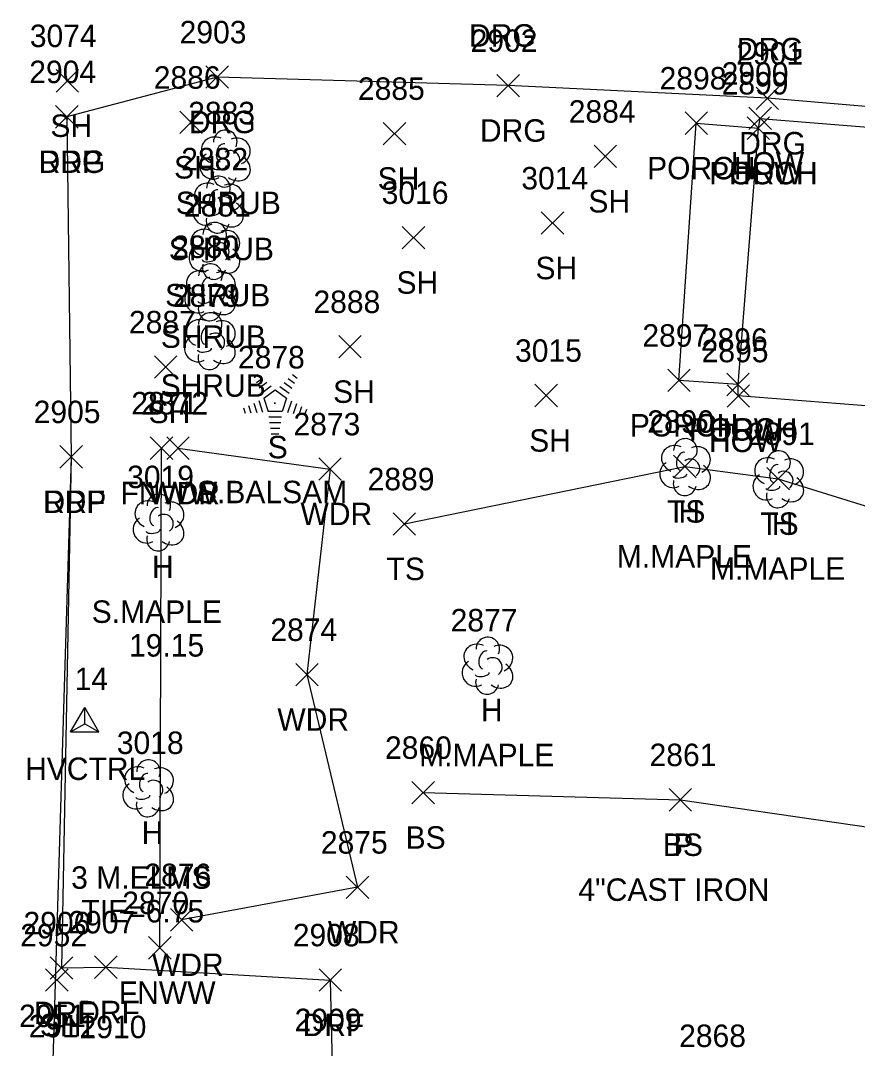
# Model space of a CAD drawing. Extents: x 1609623 to 1616187, y 756677 to 762826.
# Drawn here: x 1610617.9 to 1610692.4, y 762084.8 to 762176.3 of the extents above; entities that cross this region are included whole.
import ezdxf

# ---------------------------------------------------------------- set-up
doc = ezdxf.new("R2010")
doc.units = 0
for name, color, linetype in [('C_A', 7, 'Continuous'), ('C_I', 7, 'Continuous'), ('CPSM', 7, 'Continuous'), ('D_A', 7, 'Continuous'), ('D_C', 7, 'Continuous'), ('D_I', 7, 'Continuous'), ('D_TIC', 7, 'Continuous'), ('L_A', 7, 'Continuous'), ('L_C', 7, 'Continuous'), ('L_I', 7, 'Continuous'), ('L_TIC', 7, 'Continuous'), ('LAWA', 7, 'Continuous'), ('LBC', 7, 'Continuous'), ('LBF', 7, 'Continuous'), ('LELB', 7, 'Continuous'), ('LFNC', 7, 'Continuous'), ('LSH', 7, 'Continuous'), ('LTC', 7, 'Continuous'), ('LTD', 7, 'Continuous'), ('P_A', 7, 'Continuous'), ('P_I', 7, 'Continuous'), ('P_TIC', 7, 'Continuous'), ('PET', 7, 'Continuous'), ('R_A', 7, 'Continuous'), ('R_I', 7, 'Continuous'), ('R_TIC', 7, 'Continuous'), ('RDF', 7, 'Continuous'), ('RDG', 7, 'Continuous')]:
    doc.layers.add(name, color=color, linetype=linetype)

msp = doc.modelspace()

# ---------------------------------------------------------------- linework, layer by layer
at = {"layer": 'CPSM'}
for p, q in [((1610622.389, 762112.978), (1610623.639, 762115.143)), ((1610624.889, 762112.978), (1610623.639, 762115.143)), ((1610623.639, 762113.699), (1610623.639, 762115.143)), ((1610622.389, 762112.978), (1610623.639, 762113.699)), ((1610623.639, 762113.699), (1610623.639, 762113.699)), ((1610623.639, 762113.699), (1610624.889, 762112.978)), ((1610622.389, 762112.978), (1610624.889, 762112.978))]:
    msp.add_line(p, q, dxfattribs=at)
at = {"layer": 'D_TIC'}
for points in [[(1610675.669, 762105.935), (1610677.669, 762107.935)], [(1610677.669, 762105.935), (1610675.669, 762107.935)]]:
    msp.add_lwpolyline(points, dxfattribs=at)
at = {"layer": 'L_TIC'}
for points in [[(1610621.094, 762169.958), (1610623.094, 762171.958)], [(1610623.094, 762169.958), (1610621.094, 762171.958)], [(1610682.77, 762166.61), (1610684.77, 762168.61)], [(1610684.77, 762166.61), (1610682.77, 762168.61)], [(1610632.103, 762166.25), (1610634.103, 762168.25)], [(1610634.103, 762166.25), (1610632.103, 762168.25)], [(1610677.083, 762166.182), (1610679.083, 762168.182)], [(1610679.083, 762166.182), (1610677.083, 762168.182)], [(1610682.616, 762165.734), (1610684.616, 762167.734)], [(1610684.616, 762165.734), (1610682.616, 762167.734)], [(1610682.616, 762165.734), (1610684.616, 762167.734)], [(1610684.616, 762165.734), (1610682.616, 762167.734)], [(1610650.225, 762165.257), (1610652.225, 762167.257)], [(1610652.225, 762165.257), (1610650.225, 762167.257)], [(1610668.992, 762163.228), (1610670.992, 762165.228)], [(1610670.992, 762163.228), (1610668.992, 762165.228)], [(1610664.282, 762157.286), (1610666.282, 762159.286)], [(1610666.282, 762157.286), (1610664.282, 762159.286)], [(1610651.909, 762155.992), (1610653.909, 762157.992)], [(1610653.909, 762155.992), (1610651.909, 762157.992)], [(1610646.264, 762146.277), (1610648.264, 762148.277)], [(1610648.264, 762146.277), (1610646.264, 762148.277)], [(1610629.839, 762144.472), (1610631.839, 762146.472)], [(1610631.839, 762144.472), (1610629.839, 762146.472)], [(1610675.548, 762143.281), (1610677.548, 762145.281)], [(1610677.548, 762143.281), (1610675.548, 762145.281)], [(1610680.808, 762142.913), (1610682.808, 762144.913)], [(1610682.808, 762142.913), (1610680.808, 762144.913)], [(1610680.808, 762142.913), (1610682.808, 762144.913)], [(1610682.808, 762142.913), (1610680.808, 762144.913)], [(1610663.723, 762141.933), (1610665.723, 762143.933)], [(1610665.723, 762141.933), (1610663.723, 762143.933)], [(1610680.827, 762141.894), (1610682.827, 762143.894)], [(1610682.827, 762141.894), (1610680.827, 762143.894)], [(1610629.481, 762137.25), (1610631.481, 762139.25)], [(1610631.481, 762137.25), (1610629.481, 762139.25)], [(1610630.938, 762137.242), (1610632.938, 762139.242)], [(1610632.938, 762137.242), (1610630.938, 762139.242)], [(1610676.073, 762135.613), (1610678.073, 762137.613)], [(1610678.073, 762135.613), (1610676.073, 762137.613)], [(1610644.486, 762135.389), (1610646.486, 762137.389)], [(1610646.486, 762135.389), (1610644.486, 762137.389)], [(1610684.372, 762134.523), (1610686.372, 762136.523)], [(1610686.372, 762134.523), (1610684.372, 762136.523)], [(1610651.097, 762130.495), (1610653.097, 762132.495)], [(1610653.097, 762130.495), (1610651.097, 762132.495)], [(1610642.426, 762117.079), (1610644.426, 762119.079)], [(1610644.426, 762117.079), (1610642.426, 762119.079)], [(1610652.767, 762106.578), (1610654.767, 762108.578)], [(1610654.767, 762106.578), (1610652.767, 762108.578)], [(1610675.669, 762105.935), (1610677.669, 762107.935)], [(1610677.669, 762105.935), (1610675.669, 762107.935)], [(1610646.924, 762098.142), (1610648.924, 762100.142)], [(1610648.924, 762098.142), (1610646.924, 762100.142)], [(1610631.266, 762095.247), (1610633.266, 762097.247)], [(1610633.266, 762095.247), (1610631.266, 762097.247)], [(1610629.331, 762092.756), (1610631.331, 762094.756)], [(1610631.331, 762092.756), (1610629.331, 762094.756)], [(1610620.16, 762089.886), (1610622.16, 762091.886)], [(1610622.16, 762089.886), (1610620.16, 762091.886)]]:
    msp.add_lwpolyline(points, dxfattribs=at)
at = {"layer": 'LAWA'}
msp.add_lwpolyline([(1610631.938, 762138.242), (1610645.486, 762136.389), (1610643.426, 762118.079), (1610647.924, 762099.142), (1610632.266, 762096.247)], dxfattribs=at)
at = {"layer": 'LBC'}
msp.add_lwpolyline([(1610727.227, 762139.357), (1610681.827, 762142.894), (1610681.808, 762143.913), (1610683.616, 762166.734), (1610683.77, 762167.61), (1610729.184, 762163.947)], dxfattribs=at)
at = {"layer": 'LBF'}
msp.add_lwpolyline([(1610681.808, 762143.913), (1610676.548, 762144.281), (1610678.083, 762167.182), (1610683.616, 762166.734)], dxfattribs=at)
at = {"layer": 'LELB'}
for points in [[(1610652.097, 762131.495), (1610677.073, 762136.613), (1610685.372, 762135.523), (1610701.335, 762130.547), (1610728.082, 762124.149)], [(1610653.767, 762107.578), (1610676.669, 762106.935), (1610697.292, 762103.947), (1610720.906, 762101.238), (1610733.921, 762100.749), (1610738.119, 762077.3), (1610721.279, 762078.671), (1610704.524, 762074.696), (1610679.866, 762081.921)]]:
    msp.add_lwpolyline(points, dxfattribs=at)
at = {"layer": 'LFNC'}
msp.add_lwpolyline([(1610630.331, 762093.756), (1610630.481, 762138.25)], dxfattribs=at)
at = {"layer": 'LSH'}
for p, q in [((1610636.109, 762164.087), (1610636.109, 762164.087)), ((1610636.109, 762164.087), (1610636.109, 762164.087)), ((1610635.494, 762159.983), (1610635.494, 762159.983)), ((1610635.494, 762159.983), (1610635.494, 762159.983)), ((1610635.165, 762155.867), (1610635.165, 762155.867)), ((1610635.165, 762155.867), (1610635.165, 762155.867)), ((1610634.784, 762152.177), (1610634.784, 762152.177)), ((1610634.784, 762152.177), (1610634.784, 762152.177)), ((1610634.768, 762147.825), (1610634.768, 762147.825)), ((1610634.768, 762147.825), (1610634.768, 762147.825))]:
    msp.add_line(p, q, dxfattribs=at)
for centre in [(1610636.156, 762165.521), (1610635.541, 762161.417), (1610635.212, 762157.301), (1610634.831, 762153.611), (1610634.815, 762149.259)]:
    msp.add_arc(centre, 1.047, 335.52715, 180.95627, dxfattribs=at)
for centre, major_axis, ratio, start_param, end_param in [((1610635.318, 762164.753), (1.21, -0.512), 0.895232, 1.570796, 4.712389), ((1610637.151, 762164.67), (-1.141, -0.483), 0.949671, 1.570796, 4.712389), ((1610635.901, 762164.545), (-0.208, -0.792), 0.645439, 3.141593, 6.283185), ((1610635.026, 762163.378), (0.584, -1.042), 0.959034, 3.141593, 6.283185), ((1610636.609, 762163.92), (-0.5, 0.667), 0.989748, 3.141593, 6.283185), ((1610637.11, 762163.254), (-1.09, 0.792), 0.841452, 1.570796, 4.712389), ((1610635.651, 762163.337), (-0.625, -0.083), 0.423636, 0, 3.141593), ((1610636.11, 762162.587), (0.265, 1.061), 0.942809, 1.570796, 4.712389), ((1610634.702, 762160.649), (1.21, -0.512), 0.895232, 1.570796, 4.712389), ((1610635.286, 762160.441), (-0.208, -0.792), 0.645439, 3.141593, 6.283185), ((1610636.536, 762160.566), (-1.141, -0.483), 0.949671, 1.570796, 4.712389), ((1610635.994, 762159.816), (-0.5, 0.667), 0.989748, 3.141593, 6.283185), ((1610634.411, 762159.274), (0.584, -1.042), 0.959034, 3.141593, 6.283185), ((1610636.494, 762159.15), (-1.09, 0.792), 0.841452, 1.570796, 4.712389), ((1610635.494, 762158.483), (0.265, 1.061), 0.942809, 1.570796, 4.712389), ((1610635.036, 762159.233), (-0.625, -0.083), 0.423636, 0, 3.141593), ((1610634.373, 762156.534), (1.21, -0.512), 0.895232, 1.570796, 4.712389), ((1610636.206, 762156.451), (-1.141, -0.483), 0.949671, 1.570796, 4.712389), ((1610634.956, 762156.325), (-0.208, -0.792), 0.645439, 3.141593, 6.283185), ((1610634.082, 762155.159), (0.584, -1.042), 0.959034, 3.141593, 6.283185), ((1610635.665, 762155.701), (-0.5, 0.667), 0.989748, 3.141593, 6.283185), ((1610636.165, 762155.034), (-1.09, 0.792), 0.841452, 1.570796, 4.712389), ((1610634.707, 762155.117), (-0.625, -0.083), 0.423636, 0, 3.141593), ((1610633.993, 762152.844), (1.21, -0.512), 0.895232, 1.570796, 4.712389), ((1610635.165, 762154.367), (0.265, 1.061), 0.942809, 1.570796, 4.712389), ((1610635.826, 762152.761), (-1.141, -0.483), 0.949671, 1.570796, 4.712389), ((1610634.576, 762152.636), (-0.208, -0.792), 0.645439, 3.141593, 6.283185), ((1610633.701, 762151.469), (0.584, -1.042), 0.959034, 3.141593, 6.283185), ((1610635.284, 762152.011), (-0.5, 0.667), 0.989748, 3.141593, 6.283185), ((1610635.784, 762151.344), (-1.09, 0.792), 0.841452, 1.570796, 4.712389), ((1610634.326, 762151.427), (-0.625, -0.083), 0.423636, 0, 3.141593), ((1610634.785, 762150.677), (0.265, 1.061), 0.942809, 1.570796, 4.712389), ((1610633.976, 762148.491), (1.21, -0.512), 0.895232, 1.570796, 4.712389), ((1610635.81, 762148.408), (-1.141, -0.483), 0.949671, 1.570796, 4.712389), ((1610634.56, 762148.283), (-0.208, -0.792), 0.645439, 3.141593, 6.283185), ((1610635.268, 762147.658), (-0.5, 0.667), 0.989748, 3.141593, 6.283185), ((1610633.685, 762147.116), (0.584, -1.042), 0.959034, 3.141593, 6.283185), ((1610635.768, 762146.992), (-1.09, 0.792), 0.841452, 1.570796, 4.712389), ((1610634.31, 762147.075), (-0.625, -0.083), 0.423636, 0, 3.141593), ((1610634.768, 762146.325), (0.265, 1.061), 0.942809, 1.570796, 4.712389)]:
    msp.add_ellipse(centre, major_axis=major_axis, ratio=ratio, start_param=start_param, end_param=end_param, dxfattribs=at)
at = {"layer": 'LTC'}
for p, q in [((1610638.739, 762144.548), (1610639.093, 762144.806)), ((1610638.948, 762144.083), (1610639.477, 762144.467)), ((1610639.158, 762143.617), (1610639.862, 762144.128)), ((1610641.395, 762144.092), (1610642.074, 762143.598)), ((1610641.766, 762144.44), (1610642.315, 762144.041)), ((1610642.137, 762144.789), (1610642.556, 762144.484)), ((1610639.367, 762143.151), (1610640.246, 762143.789)), ((1610639.592, 762142.696), (1610640.604, 762143.431)), ((1610640.604, 762143.431), (1610641.601, 762142.706)), ((1610641.024, 762143.744), (1610641.833, 762143.155)), ((1610638.682, 762142.261), (1610638.953, 762141.425)), ((1610639.137, 762142.477), (1610639.468, 762141.458)), ((1610639.592, 762142.696), (1610639.979, 762141.503)), ((1610641.601, 762142.706), (1610641.209, 762141.503)), ((1610642.038, 762142.435), (1610641.7, 762141.395)), ((1610642.483, 762142.185), (1610642.195, 762141.3)), ((1610637.771, 762141.828), (1610637.923, 762141.36)), ((1610638.227, 762142.044), (1610638.438, 762141.393)), ((1610641.209, 762141.503), (1610639.979, 762141.503)), ((1610642.927, 762141.935), (1610642.69, 762141.205)), ((1610643.372, 762141.684), (1610643.185, 762141.11)), ((1610641.171, 762141.003), (1610640.027, 762141.003)), ((1610641.087, 762140.503), (1610640.099, 762140.503)), ((1610641.004, 762140.003), (1610640.172, 762140.003)), ((1610640.92, 762139.503), (1610640.245, 762139.503))]:
    msp.add_line(p, q, dxfattribs=at)
at = {"layer": 'LTD'}
for p, q in [((1610677.073, 762136.613), (1610677.073, 762136.613)), ((1610677.073, 762136.613), (1610677.073, 762136.613)), ((1610685.372, 762135.523), (1610685.372, 762135.523)), ((1610685.372, 762135.523), (1610685.372, 762135.523)), ((1610630.198, 762131.686), (1610630.198, 762131.686)), ((1610630.198, 762131.686), (1610630.198, 762131.686)), ((1610659.479, 762118.927), (1610659.479, 762118.927)), ((1610659.479, 762118.927), (1610659.479, 762118.927)), ((1610629.27, 762108.011), (1610629.27, 762108.011)), ((1610629.27, 762108.011), (1610629.27, 762108.011))]:
    msp.add_line(p, q, dxfattribs=at)
for centre in [(1610677.119, 762138.047), (1610685.419, 762136.957), (1610630.245, 762133.12), (1610659.526, 762120.361), (1610629.316, 762109.445)]:
    msp.add_arc(centre, 1.047, 335.52715, 180.95627, dxfattribs=at)
for centre, major_axis, ratio, start_param, end_param in [((1610676.281, 762137.28), (1.21, -0.512), 0.895232, 1.570796, 4.712389), ((1610678.114, 762137.197), (-1.141, -0.483), 0.949671, 1.570796, 4.712389), ((1610676.864, 762137.071), (-0.208, -0.792), 0.645439, 3.141593, 6.283185), ((1610684.581, 762136.19), (1.21, -0.512), 0.895232, 1.570796, 4.712389), ((1610675.989, 762135.905), (0.584, -1.042), 0.959034, 3.141593, 6.283185), ((1610677.573, 762136.447), (-0.5, 0.667), 0.989748, 3.141593, 6.283185), ((1610678.073, 762135.78), (-1.09, 0.792), 0.841452, 1.570796, 4.712389), ((1610685.164, 762135.982), (-0.208, -0.792), 0.645439, 3.141593, 6.283185), ((1610686.414, 762136.107), (-1.141, -0.483), 0.949671, 1.570796, 4.712389), ((1610676.614, 762135.863), (-0.625, -0.083), 0.423636, 0, 3.141593), ((1610684.289, 762134.815), (0.584, -1.042), 0.959034, 3.141593, 6.283185), ((1610685.872, 762135.357), (-0.5, 0.667), 0.989748, 3.141593, 6.283185), ((1610677.073, 762135.113), (0.265, 1.061), 0.942809, 1.570796, 4.712389), ((1610684.914, 762134.773), (-0.625, -0.083), 0.423636, 0, 3.141593), ((1610686.373, 762134.69), (-1.09, 0.792), 0.841452, 1.570796, 4.712389), ((1610685.373, 762134.023), (0.265, 1.061), 0.942809, 1.570796, 4.712389), ((1610629.406, 762132.353), (1.21, -0.512), 0.895232, 1.570796, 4.712389), ((1610629.99, 762132.144), (-0.208, -0.792), 0.645439, 3.141593, 6.283185), ((1610631.24, 762132.27), (-1.141, -0.483), 0.949671, 1.570796, 4.712389), ((1610629.115, 762130.978), (0.584, -1.042), 0.959034, 3.141593, 6.283185), ((1610630.698, 762131.519), (-0.5, 0.667), 0.989748, 3.141593, 6.283185), ((1610631.198, 762130.853), (-1.09, 0.792), 0.841452, 1.570796, 4.712389), ((1610630.198, 762130.186), (0.265, 1.061), 0.942809, 1.570796, 4.712389), ((1610629.74, 762130.936), (-0.625, -0.083), 0.423636, 0, 3.141593), ((1610658.687, 762119.593), (1.21, -0.512), 0.895232, 1.570796, 4.712389), ((1610659.27, 762119.385), (-0.208, -0.792), 0.645439, 3.141593, 6.283185), ((1610660.52, 762119.51), (-1.141, -0.483), 0.949671, 1.570796, 4.712389), ((1610658.396, 762118.218), (0.584, -1.042), 0.959034, 3.141593, 6.283185), ((1610659.979, 762118.76), (-0.5, 0.667), 0.989748, 3.141593, 6.283185), ((1610659.021, 762118.176), (-0.625, -0.083), 0.423636, 0, 3.141593), ((1610660.479, 762118.093), (-1.09, 0.792), 0.841452, 1.570796, 4.712389), ((1610659.479, 762117.427), (0.265, 1.061), 0.942809, 1.570796, 4.712389), ((1610628.478, 762108.677), (1.21, -0.512), 0.895232, 1.570796, 4.712389), ((1610629.061, 762108.469), (-0.208, -0.792), 0.645439, 3.141593, 6.283185), ((1610630.311, 762108.594), (-1.141, -0.483), 0.949671, 1.570796, 4.712389), ((1610628.186, 762107.302), (0.584, -1.042), 0.959034, 3.141593, 6.283185), ((1610629.77, 762107.844), (-0.5, 0.667), 0.989748, 3.141593, 6.283185), ((1610628.811, 762107.26), (-0.625, -0.083), 0.423636, 0, 3.141593), ((1610630.27, 762107.177), (-1.09, 0.792), 0.841452, 1.570796, 4.712389), ((1610629.27, 762106.511), (0.265, 1.061), 0.942809, 1.570796, 4.712389)]:
    msp.add_ellipse(centre, major_axis=major_axis, ratio=ratio, start_param=start_param, end_param=end_param, dxfattribs=at)
at = {"layer": 'P_TIC'}
for points in [[(1610621.044, 762166.749), (1610623.044, 762168.749)], [(1610623.044, 762166.749), (1610621.044, 762168.749)], [(1610621.434, 762136.471), (1610623.434, 762138.471)], [(1610623.434, 762136.471), (1610621.434, 762138.471)]]:
    msp.add_lwpolyline(points, dxfattribs=at)
at = {"layer": 'PET'}
msp.add_lwpolyline([(1610622.044, 762167.749), (1610622.434, 762137.471), (1610620.776, 762082.781), (1610620.24, 762051.122)], dxfattribs=at)
at = {"layer": 'R_TIC'}
for points in [[(1610634.43, 762170.29), (1610636.43, 762172.29)], [(1610636.43, 762170.29), (1610634.43, 762172.29)], [(1610660.336, 762169.529), (1610662.336, 762171.529)], [(1610662.336, 762169.529), (1610660.336, 762171.529)], [(1610683.42, 762168.399), (1610685.42, 762170.399)], [(1610685.42, 762168.399), (1610683.42, 762170.399)], [(1610621.044, 762166.749), (1610623.044, 762168.749)], [(1610623.044, 762166.749), (1610621.044, 762168.749)], [(1610621.434, 762136.471), (1610623.434, 762138.471)], [(1610623.434, 762136.471), (1610621.434, 762138.471)], [(1610620.579, 762090.958), (1610622.579, 762092.958)], [(1610622.579, 762090.958), (1610620.579, 762092.958)], [(1610624.526, 762091.036), (1610626.526, 762093.036)], [(1610626.526, 762091.036), (1610624.526, 762093.036)], [(1610644.506, 762089.888), (1610646.506, 762091.888)], [(1610646.506, 762089.888), (1610644.506, 762091.888)]]:
    msp.add_lwpolyline(points, dxfattribs=at)
at = {"layer": 'RDF'}
msp.add_lwpolyline([(1610622.434, 762137.471), (1610621.579, 762091.958), (1610625.526, 762092.036), (1610645.506, 762090.888), (1610645.675, 762083.332), (1610625.962, 762082.709), (1610620.776, 762082.781)], dxfattribs=at)
at = {"layer": 'RDG'}
for points in [[(1610684.42, 762169.399), (1610661.336, 762170.529), (1610635.43, 762171.29), (1610622.044, 762167.749)], [(1610729.495, 762165.594), (1610684.42, 762169.399)]]:
    msp.add_lwpolyline(points, dxfattribs=at)

# ---------------------------------------------------------------- texts
at = {"layer": 'C_A'}
msp.add_text('HVCTRL', height=2, dxfattribs=at).set_placement((1610618.332, 762108.699))
at = {"layer": 'C_I'}
msp.add_text('14', height=2, dxfattribs=at).set_placement((1610622.741, 762116.699))
at = {"layer": 'D_A'}
msp.add_text('P', height=2, dxfattribs=at).set_placement((1610676.047, 762101.935))
at = {"layer": 'D_C'}
msp.add_text('4"CAST IRON', height=2, dxfattribs=at).set_placement((1610667.59, 762097.935))
at = {"layer": 'D_I'}
msp.add_text('2861', height=2, dxfattribs=at).set_placement((1610673.929, 762109.935))
at = {"layer": 'L_A'}
for s, p in [('SH', (1610620.582, 762165.958)), ('SH', (1610631.591, 762162.25)), ('PORCH', (1610673.705, 762162.182)), ('HOW', (1610681.156, 762162.61)), ('SH', (1610649.713, 762161.257)), ('PORCH', (1610679.238, 762161.734)), ('HOW', (1610681.001, 762161.734)), ('SHRUB', (1610631.739, 762159.087)), ('SH', (1610668.48, 762159.228)), ('SHRUB', (1610631.124, 762154.983)), ('SH', (1610663.77, 762153.286)), ('SH', (1610651.397, 762151.992)), ('SHRUB', (1610630.795, 762150.867)), ('SHRUB', (1610630.414, 762147.177)), ('SHRUB', (1610630.398, 762142.825)), ('SH', (1610645.752, 762142.277)), ('SH', (1610629.327, 762140.472)), ('PORCH', (1610672.17, 762139.281)), ('PORCH', (1610677.43, 762138.913)), ('HOW', (1610679.193, 762138.913)), ('S', (1610639.929, 762137.34)), ('SH', (1610663.211, 762137.933)), ('HOW', (1610679.213, 762137.894)), ('FNWW', (1610626.827, 762133.25)), ('WDR', (1610629.3, 762133.242)), ('WDR', (1610642.848, 762131.389)), ('TS', (1610675.482, 762131.613)), ('H', (1610676.506, 762131.613)), ('TS', (1610683.782, 762130.523)), ('H', (1610684.806, 762130.523)), ('H', (1610629.631, 762126.686)), ('TS', (1610650.506, 762126.495)), ('H', (1610658.912, 762113.927)), ('WDR', (1610640.788, 762113.079)), ('H', (1610628.703, 762103.011)), ('BS', (1610652.208, 762102.578)), ('BS', (1610675.11, 762101.935)), ('WDR', (1610645.287, 762094.142)), ('WDR', (1610629.628, 762091.247)), ('FNWW', (1610626.677, 762088.756)), ('SH', (1610619.649, 762085.886))]:
    msp.add_text(s, height=2, dxfattribs=at).set_placement(p)
at = {"layer": 'L_C'}
for s, p in [('S.BALSAM', (1610633.63, 762133.34)), ('M.MAPLE', (1610671.01, 762127.613)), ('M.MAPLE', (1610679.309, 762126.523)), ('S.MAPLE', (1610624.261, 762122.686)), ('19.15', (1610627.584, 762119.686)), ('M.MAPLE', (1610653.416, 762109.927)), ('3 M.ELMS', (1610622.435, 762099.011)), ('TIE=6.75', (1610623.348, 762096.011))]:
    msp.add_text(s, height=2, dxfattribs=at).set_placement(p)
at = {"layer": 'L_I'}
for s, p in [('3074', (1610618.755, 762173.958)), ('2886', (1610629.788, 762170.25)), ('2900', (1610680.345, 762170.61)), ('2898', (1610674.823, 762170.182)), ('2899', (1610680.348, 762169.734)), ('2899', (1610680.348, 762169.734)), ('2885', (1610647.965, 762169.257)), ('2883', (1610632.85, 762167.087)), ('2884', (1610666.732, 762167.228)), ('2882', (1610632.234, 762162.983)), ('3014', (1610662.51, 762161.286)), ('3016', (1610650.082, 762159.992)), ('2881', (1610632.472, 762158.867)), ('2880', (1610631.438, 762155.177)), ('2879', (1610631.501, 762150.825)), ('2888', (1610644.004, 762150.277)), ('2887', (1610627.579, 762148.472)), ('2897', (1610673.288, 762147.281)), ('2896', (1610678.493, 762146.913)), ('2896', (1610678.493, 762146.913)), ('3015', (1610661.951, 762145.933)), ('2895', (1610678.567, 762145.894)), ('2878', (1610637.284, 762145.34)), ('2871', (1610627.788, 762141.25)), ('2872', (1610628.678, 762141.242)), ('2873', (1610642.226, 762139.389)), ('2890', (1610673.726, 762139.613)), ('2890', (1610673.726, 762139.613)), ('2891', (1610682.68, 762138.523)), ('2891', (1610682.68, 762138.523)), ('3019', (1610627.418, 762134.686)), ('2889', (1610648.829, 762134.495)), ('2877', (1610656.219, 762121.927)), ('2874', (1610640.166, 762121.079)), ('3018', (1610626.498, 762111.011)), ('2860', (1610650.373, 762110.578)), ('2861', (1610673.929, 762109.935)), ('2875', (1610644.665, 762102.142)), ('2876', (1610628.951, 762099.247)), ('2870', (1610626.984, 762096.756)), ('2952', (1610617.9, 762093.886)), ('2951', (1610617.794, 762086.696)), ('2868', (1610676.559, 762084.921))]:
    msp.add_text(s, height=2, dxfattribs=at).set_placement(p)
at = {"layer": 'LTC'}
msp.add_text('.', height=1.037, rotation=270, dxfattribs=at).set_placement((1610640.486, 762142.444))
at = {"layer": 'P_A'}
for p in [(1610619.533, 762162.749), (1610619.922, 762132.471)]:
    msp.add_text('RDP', height=2, dxfattribs=at).set_placement(p)
at = {"layer": 'P_I'}
for s, p in [('2904', (1610618.706, 762170.749)), ('2905', (1610619.095, 762140.471)), ('2911', (1610618.65, 762085.781))]:
    msp.add_text(s, height=2, dxfattribs=at).set_placement(p)
at = {"layer": 'R_A'}
for s, p in [('DRG', (1610657.854, 762173.995)), ('DRG', (1610681.698, 762172.776)), ('DRG', (1610632.918, 762166.29)), ('DRG', (1610658.824, 762165.529)), ('DRG', (1610681.908, 762164.399)), ('DRG', (1610619.533, 762162.749)), ('DRF', (1610619.969, 762132.471)), ('DRF', (1610623.062, 762087.036)), ('DRF', (1610619.114, 762086.958)), ('DRF', (1610643.041, 762085.888))]:
    msp.add_text(s, height=2, dxfattribs=at).set_placement(p)
at = {"layer": 'R_I'}
for s, p in [('2903', (1610632.091, 762174.29)), ('2902', (1610657.997, 762173.529)), ('2901', (1610681.648, 762172.399)), ('2904', (1610618.706, 762170.749)), ('2905', (1610619.095, 762140.471)), ('2906', (1610618.185, 762094.958)), ('2907', (1610622.188, 762095.036)), ('2908', (1610642.167, 762093.888)), ('2909', (1610642.328, 762086.332)), ('2911', (1610618.65, 762085.781)), ('2910', (1610623.183, 762085.709))]:
    msp.add_text(s, height=2, dxfattribs=at).set_placement(p)

doc.saveas('drawing.dxf')
